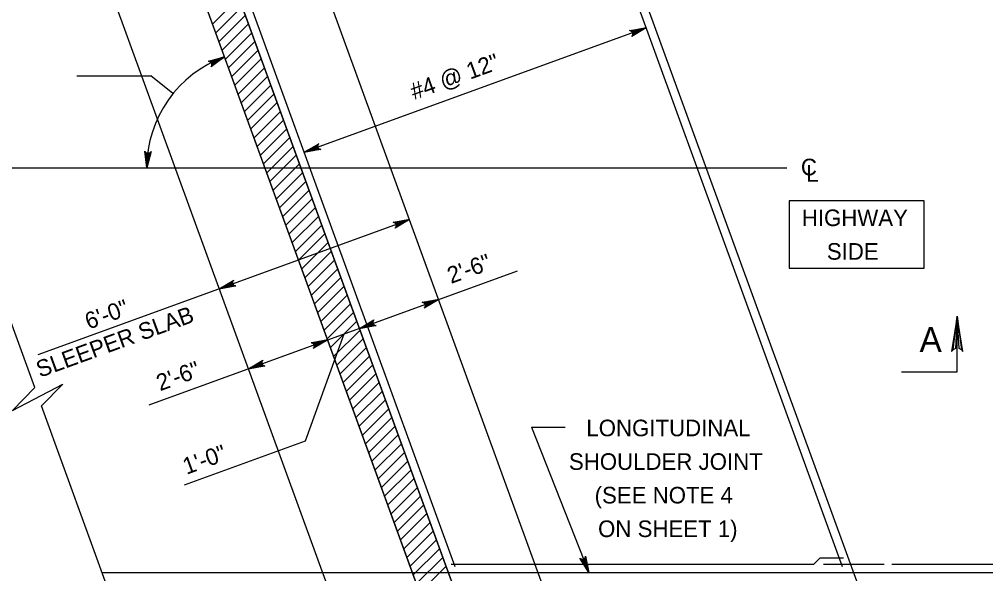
# Model space of a CAD drawing. Extents: x 2084213 to 2099800, y 976677 to 981262.
# Drawn here: x 2094533 to 2095105, y 977781 to 978110 of the extents above; entities that cross this region are included whole.
import ezdxf

# ---------------------------------------------------------------- set-up
doc = ezdxf.new("R2010")
doc.units = 0
doc.layers.add('1', color=7, linetype='Continuous')

msp = doc.modelspace()

# ---------------------------------------------------------------- linework, layer by layer
at = {"layer": '1'}
for p, q in [((2094769.84, 977623.52), (2094479.88, 978420.18)), ((2094823.05, 977623.52), (2094533.09, 978420.18)), ((2094897.54, 977623.52), (2094607.58, 978420.18)), ((2095084.34, 977623.52), (2094794.37, 978420.18)), ((2094830.36, 977661.91), (2094574.19, 978365.74)), ((2094790.81, 977785.18), (2094618.54, 978258.52)), ((2095020.17, 977785.18), (2094847.89, 978258.52)), ((2094647.06, 978107.04), (2094662.67, 978122.65)), ((2094648.95, 978101.86), (2094664.55, 978117.46)), ((2094650.84, 978096.68), (2094666.44, 978112.28)), ((2094652.72, 978091.49), (2094668.33, 978107.1)), ((2094903.86, 978104.76), (2094701.33, 978031.04)), ((2094654.61, 978086.31), (2094670.21, 978101.91)), ((2094656.5, 978081.12), (2094672.1, 978096.73)), ((2094658.38, 978075.94), (2094673.99, 978091.54)), ((2094660.27, 978070.75), (2094675.87, 978086.36)), ((2094566.67, 978076.39), (2094610.47, 978076.39)), ((2094623.59, 978065.81), (2094610.47, 978076.39)), ((2094662.16, 978065.57), (2094677.76, 978081.17)), ((2094664.04, 978060.39), (2094679.65, 978075.99)), ((2094665.93, 978055.2), (2094681.54, 978070.81)), ((2094667.82, 978050.02), (2094683.42, 978065.62)), ((2094541.74, 977891.47), (2094478.9, 978064.14)), ((2094669.71, 978044.83), (2094685.31, 978060.44)), ((2094671.59, 978039.65), (2094687.2, 978055.25)), ((2094673.48, 978034.47), (2094689.08, 978050.07)), ((2094675.37, 978029.28), (2094690.97, 978044.89)), ((2094677.25, 978024.1), (2094692.86, 978039.7)), ((2094679.14, 978018.91), (2094694.74, 978034.52)), ((2094681.03, 978013.73), (2094696.63, 978029.33)), ((2094682.91, 978008.54), (2094698.52, 978024.15)), ((2094460.07, 978021.85), (2094987.07, 978021.85)), ((2094684.8, 978003.36), (2094700.4, 978018.96)), ((2094686.69, 977998.18), (2094702.29, 978013.78)), ((2094688.57, 977992.99), (2094704.18, 978008.6)), ((2094690.46, 977987.81), (2094706.07, 978003.41)), ((2094692.35, 977982.62), (2094707.95, 977998.23)), ((2094543.65, 977911.09), (2094763.72, 977991.19)), ((2094694.23, 977977.44), (2094709.84, 977993.04)), ((2094696.12, 977972.26), (2094711.73, 977987.86)), ((2094698.01, 977967.07), (2094713.61, 977982.68)), ((2094699.9, 977961.89), (2094715.5, 977977.49)), ((2094701.78, 977956.7), (2094717.39, 977972.31)), ((2094703.67, 977951.52), (2094719.27, 977967.12)), ((2094705.56, 977946.33), (2094721.16, 977961.94)), ((2094609.45, 977881.26), (2094827.68, 977960.69)), ((2094707.44, 977941.15), (2094723.05, 977956.75)), ((2094709.33, 977935.97), (2094724.93, 977951.57)), ((2094711.22, 977930.78), (2094726.82, 977946.39)), ((2094713.1, 977925.6), (2094728.71, 977941.2)), ((2094714.99, 977920.41), (2094730.59, 977936.02)), ((2094716.88, 977915.23), (2094732.48, 977930.83)), ((2094702.12, 977860.01), (2094724.98, 977923.31)), ((2094718.76, 977910.05), (2094734.37, 977925.65)), ((2094720.65, 977904.86), (2094736.26, 977920.46)), ((2094722.54, 977899.68), (2094738.14, 977915.28)), ((2094724.43, 977894.49), (2094740.03, 977910.1)), ((2094726.31, 977889.31), (2094741.92, 977904.91)), ((2094728.2, 977884.12), (2094743.8, 977899.73)), ((2094730.09, 977878.94), (2094745.69, 977894.54)), ((2094731.97, 977873.76), (2094747.58, 977889.36)), ((2094733.86, 977868.57), (2094749.46, 977884.18)), ((2094605.51, 977716.26), (2094545.69, 977880.63)), ((2094735.75, 977863.39), (2094751.35, 977878.99)), ((2094737.63, 977858.2), (2094753.24, 977873.81)), ((2094739.52, 977853.02), (2094755.12, 977868.62)), ((2094835.95, 977868.07), (2094869.87, 977781.85)), ((2094835.95, 977868.07), (2094855.94, 977868.07)), ((2094630.39, 977833.9), (2094702.12, 977860.01)), ((2094741.41, 977847.83), (2094757.01, 977863.44)), ((2094743.29, 977842.65), (2094758.9, 977858.25)), ((2094745.18, 977837.47), (2094760.78, 977853.07)), ((2094747.07, 977832.28), (2094762.67, 977847.89)), ((2094748.95, 977827.1), (2094764.56, 977842.7)), ((2094750.84, 977821.91), (2094766.45, 977837.52)), ((2094752.73, 977816.73), (2094768.33, 977832.33)), ((2094754.62, 977811.55), (2094770.22, 977827.15)), ((2094756.5, 977806.36), (2094772.11, 977821.97)), ((2094758.39, 977801.18), (2094773.99, 977816.78)), ((2094760.28, 977795.99), (2094775.88, 977811.6)), ((2094762.16, 977790.81), (2094777.77, 977806.41)), ((2094764.05, 977785.62), (2094779.65, 977801.23)), ((2094765.94, 977780.44), (2094781.54, 977796.04)), ((2094767.82, 977775.26), (2094783.43, 977790.86)), ((2095006.86, 977790.48), (2095003.22, 977786.85)), ((2095006.86, 977790.48), (2095020.73, 977790.48)), ((2094769.71, 977770.07), (2094785.31, 977785.68)), ((2094788.44, 977786.85), (2095003.22, 977786.85)), ((2095008.89, 977786.85), (2095044.89, 977786.85)), ((2095049.27, 977786.85), (2095180.61, 977786.85)), ((2094581.64, 977781.85), (2095284.34, 977781.85))]:
    msp.add_line(p, q, dxfattribs=at)
for points in [[(2094838.18, 977640.44), (2094844.34, 977623.52), (2094823.05, 977623.52), (2094533.09, 978420.18), (2094554.37, 978420.18), (2094829.85, 977663.3)], [(2094903.86, 978104.76), (2094895.29, 978099.69), (2094895.55, 978100.06), (2094895.82, 978100.44), (2094895.89, 978100.81), (2094895.96, 978101.19), (2094895.9, 978101.51), (2094895.84, 978101.84), (2094895.68, 978102.13), (2094895.51, 978102.42), (2094895.22, 978102.66), (2094894.92, 978102.9), (2094894.48, 978103.02), (2094894.03, 978103.14), (2094903.86, 978104.76), (2094894.48, 978103.02), (2094894.92, 978102.9), (2094903.86, 978104.76), (2094895.22, 978102.66), (2094895.51, 978102.42), (2094903.86, 978104.76), (2094895.68, 978102.13), (2094895.84, 978101.84), (2094903.86, 978104.76), (2094895.9, 978101.51), (2094895.96, 978101.19), (2094903.86, 978104.76), (2094895.89, 978100.81), (2094895.82, 978100.44), (2094903.86, 978104.76), (2094895.55, 978100.06)], [(2094654.13, 978087.63), (2094646.16, 978081.66), (2094646.38, 978082.06), (2094646.61, 978082.46), (2094646.64, 978082.84), (2094646.67, 978083.22), (2094646.57, 978083.54), (2094646.48, 978083.86), (2094646.28, 978084.13), (2094646.09, 978084.4), (2094645.77, 978084.61), (2094645.45, 978084.82), (2094644.99, 978084.88), (2094644.54, 978084.95), (2094654.13, 978087.63), (2094644.99, 978084.88), (2094645.45, 978084.82), (2094654.13, 978087.63), (2094645.77, 978084.61), (2094646.09, 978084.4), (2094654.13, 978087.63), (2094646.28, 978084.13), (2094646.48, 978083.86), (2094654.13, 978087.63), (2094646.57, 978083.54), (2094646.67, 978083.22), (2094654.13, 978087.63), (2094646.64, 978082.84), (2094646.61, 978082.46), (2094654.13, 978087.63), (2094646.38, 978082.06)], [(2094701.33, 978031.04), (2094709.9, 978036.11), (2094709.63, 978035.74), (2094709.37, 978035.37), (2094709.3, 978034.99), (2094709.23, 978034.62), (2094709.29, 978034.29), (2094709.34, 978033.96), (2094709.51, 978033.67), (2094709.67, 978033.38), (2094709.97, 978033.14), (2094710.26, 978032.9), (2094710.71, 978032.78), (2094711.15, 978032.67), (2094701.33, 978031.04), (2094710.71, 978032.78), (2094710.26, 978032.9), (2094701.33, 978031.04), (2094709.97, 978033.14), (2094709.67, 978033.38), (2094701.33, 978031.04), (2094709.51, 978033.67), (2094709.34, 978033.96), (2094701.33, 978031.04), (2094709.29, 978034.29), (2094709.23, 978034.62), (2094701.33, 978031.04), (2094709.3, 978034.99), (2094709.37, 978035.37), (2094701.33, 978031.04), (2094709.63, 978035.74)], [(2094608.07, 978021.85), (2094606.95, 978031.74), (2094607.18, 978031.35), (2094607.42, 978030.95), (2094607.73, 978030.73), (2094608.04, 978030.52), (2094608.36, 978030.44), (2094608.69, 978030.36), (2094609.02, 978030.39), (2094609.35, 978030.42), (2094609.69, 978030.59), (2094610.03, 978030.76), (2094610.32, 978031.12), (2094610.61, 978031.48), (2094608.07, 978021.85), (2094610.32, 978031.12), (2094610.03, 978030.76), (2094608.07, 978021.85), (2094609.69, 978030.59), (2094609.35, 978030.42), (2094608.07, 978021.85), (2094609.02, 978030.39), (2094608.69, 978030.36), (2094608.07, 978021.85), (2094608.36, 978030.44), (2094608.04, 978030.52), (2094608.07, 978021.85), (2094607.73, 978030.73), (2094607.42, 978030.95), (2094608.07, 978021.85), (2094607.18, 978031.35)], [(2094763.72, 977991.19), (2094755.15, 977986.12), (2094755.42, 977986.5), (2094755.68, 977986.87), (2094755.75, 977987.25), (2094755.82, 977987.62), (2094755.76, 977987.95), (2094755.71, 977988.28), (2094755.54, 977988.57), (2094755.38, 977988.85), (2094755.08, 977989.1), (2094754.79, 977989.34), (2094754.34, 977989.45), (2094753.9, 977989.57), (2094763.72, 977991.19), (2094754.34, 977989.45), (2094754.79, 977989.34), (2094763.72, 977991.19), (2094755.08, 977989.1), (2094755.38, 977988.85), (2094763.72, 977991.19), (2094755.54, 977988.57), (2094755.71, 977988.28), (2094763.72, 977991.19), (2094755.76, 977987.95), (2094755.82, 977987.62), (2094763.72, 977991.19), (2094755.75, 977987.25), (2094755.68, 977986.87), (2094763.72, 977991.19), (2094755.42, 977986.5)], [(2094650.96, 977950.15), (2094659.53, 977955.22), (2094659.26, 977954.85), (2094659, 977954.47), (2094658.93, 977954.1), (2094658.86, 977953.72), (2094658.91, 977953.4), (2094658.97, 977953.07), (2094659.14, 977952.78), (2094659.3, 977952.49), (2094659.6, 977952.25), (2094659.89, 977952.01), (2094660.34, 977951.89), (2094660.78, 977951.77), (2094650.96, 977950.15), (2094660.34, 977951.89), (2094659.89, 977952.01), (2094650.96, 977950.15), (2094659.6, 977952.25), (2094659.3, 977952.49), (2094650.96, 977950.15), (2094659.14, 977952.78), (2094658.97, 977953.07), (2094650.96, 977950.15), (2094658.91, 977953.4), (2094658.86, 977953.72), (2094650.96, 977950.15), (2094658.93, 977954.1), (2094659, 977954.47), (2094650.96, 977950.15), (2094659.26, 977954.85)], [(2094781.01, 977943.7), (2094772.44, 977938.63), (2094772.7, 977939.01), (2094772.97, 977939.38), (2094773.04, 977939.76), (2094773.11, 977940.13), (2094773.05, 977940.46), (2094772.99, 977940.79), (2094772.83, 977941.08), (2094772.66, 977941.36), (2094772.37, 977941.61), (2094772.07, 977941.85), (2094771.63, 977941.96), (2094771.18, 977942.08), (2094781.01, 977943.7), (2094771.63, 977941.96), (2094772.07, 977941.85), (2094781.01, 977943.7), (2094772.37, 977941.61), (2094772.66, 977941.36), (2094781.01, 977943.7), (2094772.83, 977941.08), (2094772.99, 977940.79), (2094781.01, 977943.7), (2094773.05, 977940.46), (2094773.11, 977940.13), (2094781.01, 977943.7), (2094773.04, 977939.76), (2094772.97, 977939.38), (2094781.01, 977943.7), (2094772.7, 977939.01)], [(2095055.02, 977900.87), (2095088.09, 977900.87), (2095088.09, 977933.94)], [(2095090.6, 977913.92), (2095089.16, 977914.67), (2095088.09, 977933.94), (2095090.6, 977913.92), (2095091.48, 977912.9), (2095088.09, 977933.94), (2095087.14, 977914.68), (2095085.7, 977913.98), (2095088.09, 977933.94), (2095084.75, 977912.9), (2095085.7, 977913.98)], [(2094734.02, 977926.6), (2094742.59, 977931.67), (2094742.32, 977931.3), (2094742.06, 977930.92), (2094741.99, 977930.55), (2094741.92, 977930.18), (2094741.98, 977929.85), (2094742.04, 977929.52), (2094742.2, 977929.23), (2094742.37, 977928.94), (2094742.66, 977928.7), (2094742.96, 977928.46), (2094743.4, 977928.34), (2094743.84, 977928.23), (2094734.02, 977926.6), (2094743.4, 977928.34), (2094742.96, 977928.46), (2094734.02, 977926.6), (2094742.66, 977928.7), (2094742.37, 977928.94), (2094734.02, 977926.6), (2094742.2, 977929.23), (2094742.04, 977929.52), (2094734.02, 977926.6), (2094741.98, 977929.85), (2094741.92, 977930.18), (2094734.02, 977926.6), (2094741.99, 977930.55), (2094742.06, 977930.92), (2094734.02, 977926.6), (2094742.32, 977931.3)], [(2094715.23, 977919.76), (2094706.66, 977914.69), (2094706.92, 977915.07), (2094707.19, 977915.44), (2094707.26, 977915.81), (2094707.33, 977916.19), (2094707.27, 977916.52), (2094707.21, 977916.84), (2094707.05, 977917.13), (2094706.88, 977917.42), (2094706.59, 977917.66), (2094706.29, 977917.91), (2094705.85, 977918.02), (2094705.4, 977918.14), (2094715.23, 977919.76), (2094705.85, 977918.02), (2094706.29, 977917.91), (2094715.23, 977919.76), (2094706.59, 977917.66), (2094706.88, 977917.42), (2094715.23, 977919.76), (2094707.05, 977917.13), (2094707.21, 977916.84), (2094715.23, 977919.76), (2094707.27, 977916.52), (2094707.33, 977916.19), (2094715.23, 977919.76), (2094707.26, 977915.81), (2094707.19, 977915.44), (2094715.23, 977919.76), (2094706.92, 977915.07)], [(2094668.24, 977902.66), (2094676.81, 977907.73), (2094676.55, 977907.36), (2094676.28, 977906.98), (2094676.21, 977906.61), (2094676.14, 977906.23), (2094676.2, 977905.91), (2094676.26, 977905.58), (2094676.42, 977905.29), (2094676.59, 977905), (2094676.88, 977904.76), (2094677.18, 977904.52), (2094677.62, 977904.4), (2094678.07, 977904.28), (2094668.24, 977902.66), (2094677.62, 977904.4), (2094677.18, 977904.52), (2094668.24, 977902.66), (2094676.88, 977904.76), (2094676.59, 977905), (2094668.24, 977902.66), (2094676.42, 977905.29), (2094676.26, 977905.58), (2094668.24, 977902.66), (2094676.2, 977905.91), (2094676.14, 977906.23), (2094668.24, 977902.66), (2094676.21, 977906.61), (2094676.28, 977906.98), (2094668.24, 977902.66), (2094676.55, 977907.36)], [(2094541.74, 977891.47), (2094528.58, 977877.85), (2094558.35, 977893.44), (2094545.67, 977880.61)], [(2094869.87, 977781.85), (2094864.58, 977790.28), (2094864.97, 977790.03), (2094865.35, 977789.77), (2094865.72, 977789.71), (2094866.1, 977789.65), (2094866.43, 977789.72), (2094866.75, 977789.79), (2094867.04, 977789.96), (2094867.32, 977790.13), (2094867.56, 977790.43), (2094867.79, 977790.73), (2094867.89, 977791.18), (2094868, 977791.63), (2094869.87, 977781.85), (2094867.89, 977791.18), (2094867.79, 977790.73), (2094869.87, 977781.85), (2094867.56, 977790.43), (2094867.32, 977790.13), (2094869.87, 977781.85), (2094867.04, 977789.96), (2094866.75, 977789.79), (2094869.87, 977781.85), (2094866.43, 977789.72), (2094866.1, 977789.65), (2094869.87, 977781.85), (2094865.72, 977789.71), (2094865.35, 977789.77), (2094869.87, 977781.85), (2094864.97, 977790.03)]]:
    msp.add_lwpolyline(points, dxfattribs=at)
msp.add_lwpolyline([(2094988.57, 977962.27), (2095068.57, 977962.27), (2095068.57, 978002.27), (2094988.57, 978002.27)], close=True, dxfattribs=at)
msp.add_arc((2094678.07, 978021.85), 70, 110, 180, dxfattribs=at)

# ---------------------------------------------------------------- texts
for s, height, p in [('#4 @ 12"', 9.843, (2094766.38, 978061.98)), ('2\'-6"', 9.843, (2094788.24, 977952.94)), ('SLEEPER SLAB', 9.8425, (2094544.75, 977897.3)), ('6\'-0"', 9.843, (2094573.63, 977925.85)), ('2\'-6"', 9.843, (2094615.92, 977889.29)), ('1\'-0"', 9.843, (2094631.55, 977839.78))]:
    msp.add_text(s, height=height, rotation=20, dxfattribs=at).set_placement(p)
for s, height, p in [('C', 9.84, (2094995.5, 978017.35)), ('L', 9.84, (2094998.66, 978013.57)), ('HIGHWAY', 9.843, (2094996.02, 977987.25)), ('SIDE', 9.843, (2095010.86, 977967.33)), ('A', 14.76, (2095065.78, 977912.64)), ('LONGITUDINAL', 9.8425, (2094868.41, 977862.65)), ('SHOULDER JOINT', 9.8425, (2094858.1, 977842.73)), ('(SEE NOTE 4', 9.8425, (2094873.33, 977822.81)), ('ON SHEET 1)', 9.8425, (2094875.35, 977802.88))]:
    msp.add_text(s, height=height, dxfattribs=at).set_placement(p)

doc.saveas('drawing.dxf')
